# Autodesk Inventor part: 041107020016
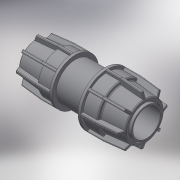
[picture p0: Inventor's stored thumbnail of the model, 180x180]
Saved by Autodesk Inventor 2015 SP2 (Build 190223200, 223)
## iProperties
Created: 2017-08
Part Number: 041107020016
Material: Generic
Description: PLASSON IRRIFIT REDUCER 20-16
Document SubType Name: Modeling
Designer: KIM
Density: 1 g/cm^3
Appearance: Default
Author: KIM
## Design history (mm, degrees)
derived "041107.ipt"
feature "Solid1::041107.ipt"
tag "TaggingFeature1"
body "Solid1"
other parameters: "d5" = 30.8, "d6" = 18.26, "d10" = 39, "d22" = 28, "d24" = 1.909, "d25" = 35.1, "d26" = 31.2, "d31" = 0.8, "d49" = 1.95, "d50" = 0, "d58" = 0.4, "d61" = 360 deg, "d78" = 5 deg, "d80" = 22, "d81" = 41.5, "d82" = 2.49, "d84" = 5 deg, "d85" = 70 deg, "d86" = 37.05, "d87" = 0.415, "d88" = 0, "d89" = 33.15, "d90" = 4.15, "d91" = 0, "d100" = 34, "d102" = 30.6, "d103" = 16, "d104" = 17.6, "d105" = 5 deg, "d106" = 18.26, "d107" = 27.2, "d108" = 2.49, "d109" = 41.5, "d110" = 1.909, "d111" = 30.8, "d112" = 24.64, "d113" = 70 deg, "d114" = 5 deg, "E_" = 39, "H_" = 83, "l_nut" = 30.8, "E_1" = 34, "d_1" = 16
